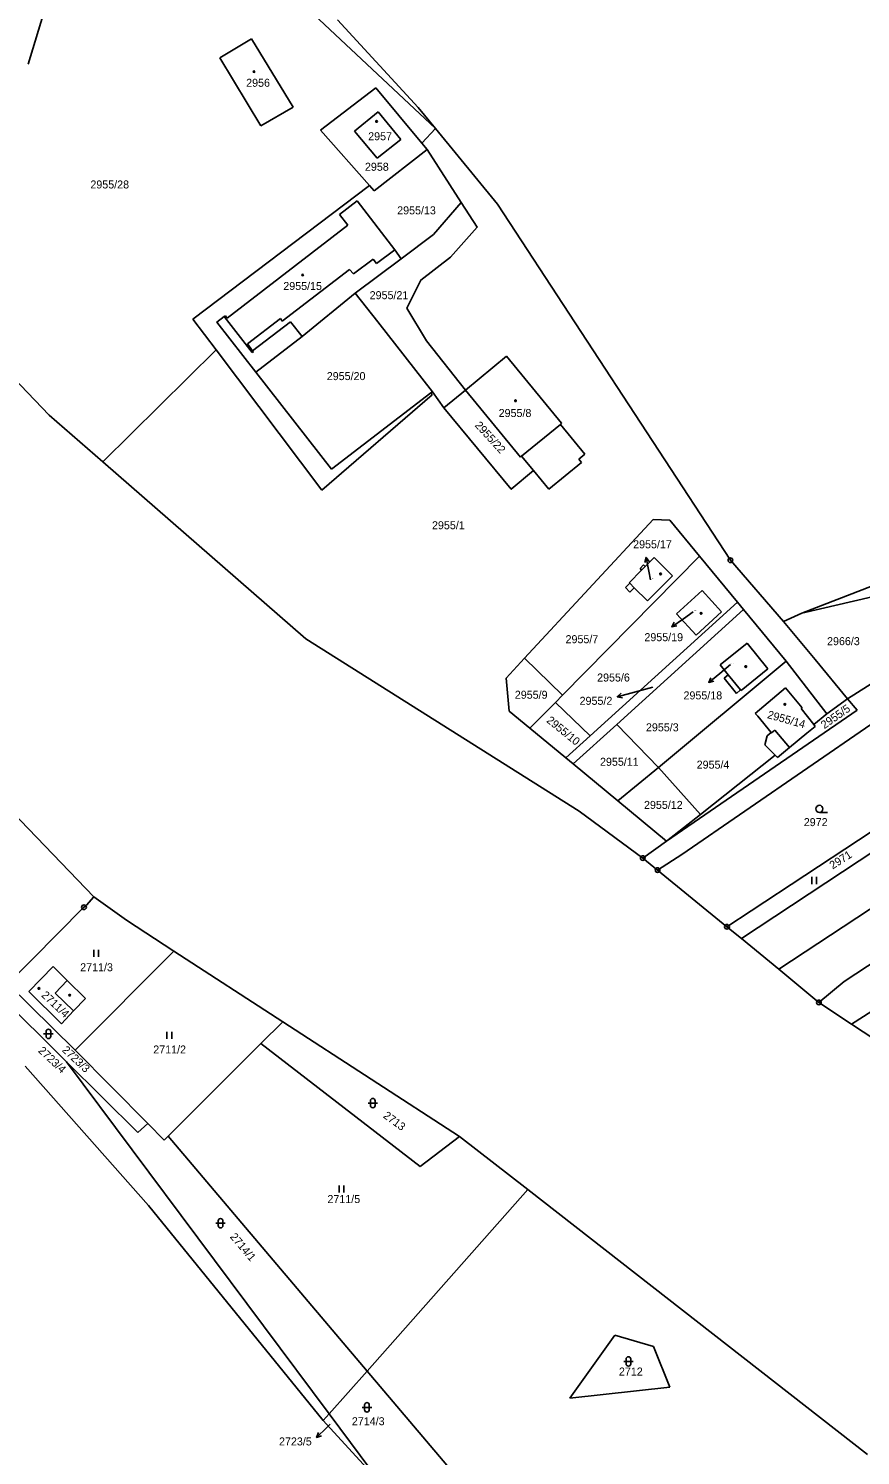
# Model space of a CAD drawing. Extents: x -736345 to -729997, y -1130177 to -1122501.
# Drawn here: x -734414.3 to -734237.6, y -1124788.5 to -1124485.4 of the extents above; entities that cross this region are included whole.
import ezdxf

# ---------------------------------------------------------------- set-up
doc = ezdxf.new("R2010")
doc.units = 0
for name, color, linetype in [('Vrstva 1', 7, 'Continuous'), ('Vrstva 16', 7, 'Continuous'), ('Vrstva 18', 7, 'Continuous'), ('Vrstva 19', 7, 'Continuous'), ('Vrstva 25', 7, 'Continuous'), ('Vrstva 4', 7, 'Continuous')]:
    doc.layers.add(name, color=color, linetype=linetype)

msp = doc.modelspace()

# ---------------------------------------------------------------- linework, layer by layer
at = {"layer": 'Vrstva 1'}
for points in [[(-734371.6, -1124465.53), (-734327.88, -1124506.56)], [(-734410.71, -1124480.82), (-734414.4, -1124492.92)], [(-734348.65, -1124483.52), (-734331.53, -1124502.1)], [(-734366.96, -1124487.53), (-734373.7, -1124491.59)], [(-734358.11, -1124502.09), (-734366.96, -1124487.53)], [(-734373.7, -1124491.59), (-734364.99, -1124506.04)], [(-734340.52, -1124497.94), (-734352.28, -1124506.96)], [(-734330.77, -1124509.7), (-734340.52, -1124497.94)], [(-734358.11, -1124502.09), (-734364.99, -1124506.04)], [(-734331.53, -1124502.1), (-734327.88, -1124506.56)], [(-734345.1, -1124507.19), (-734340.05, -1124503.04)], [(-734340.05, -1124503.04), (-734335.23, -1124508.9)], [(-734352.28, -1124506.96), (-734341.9, -1124518.71)], [(-734340.28, -1124512.86), (-734345.1, -1124507.19)], [(-734330.77, -1124509.7), (-734327.88, -1124506.56)], [(-734327.88, -1124506.56), (-734314.66, -1124522.69)], [(-734329.63, -1124511.08), (-734340.88, -1124519.86)], [(-734335.23, -1124508.9), (-734340.28, -1124512.86)], [(-734329.63, -1124511.08), (-734330.77, -1124509.7)], [(-734329.63, -1124511.08), (-734322.38, -1124522.3)], [(-734341.9, -1124518.71), (-734379.41, -1124547.08)], [(-734340.88, -1124519.86), (-734341.9, -1124518.71)], [(-734348.24, -1124524.87), (-734344.49, -1124521.99)], [(-734344.49, -1124521.99), (-734336.52, -1124532.37)], [(-734322.38, -1124522.3), (-734328.26, -1124529.11), (-734335.13, -1124534.26)], [(-734322.38, -1124522.3), (-734319, -1124527.54), (-734324.64, -1124533.95), (-734330.99, -1124538.79), (-734333.97, -1124544.77), (-734329.79, -1124551.72), (-734321.5, -1124562.16)], [(-734265.19, -1124598.32), (-734314.66, -1124522.69)], [(-734346.48, -1124527.16), (-734348.24, -1124524.87)], [(-734372.15, -1124546.86), (-734346.48, -1124527.16)], [(-734336.52, -1124532.37), (-734335.13, -1124534.26)], [(-734335.13, -1124534.26), (-734344.91, -1124541.55)], [(-734344.91, -1124541.55), (-734356.16, -1124550.76)], [(-734340.13, -1124547.66), (-734344.91, -1124541.55)], [(-734379.41, -1124547.08), (-734374.49, -1124553.6)], [(-734366.04, -1124558.32), (-734374.3, -1124547.72), (-734372.78, -1124546.53)], [(-734372.78, -1124546.53), (-734372.51, -1124546.39)], [(-734372.51, -1124546.39), (-734372.15, -1124546.86)], [(-734328.52, -1124562.5), (-734340.13, -1124547.66)], [(-734366.04, -1124558.32), (-734356.16, -1124550.76)], [(-734398.52, -1124577.43), (-734374.49, -1124553.6)], [(-734374.49, -1124553.6), (-734351.99, -1124583.41)], [(-734312.74, -1124554.97), (-734321.5, -1124562.16)], [(-734301.06, -1124569.21), (-734312.74, -1124554.97)], [(-734409.96, -1124567.46), (-734419.08, -1124557.96)], [(-734349.96, -1124578.95), (-734366.04, -1124558.32)], [(-734351.99, -1124583.41), (-734328.55, -1124563.18)], [(-734328.87, -1124562.77), (-734349.96, -1124578.95)], [(-734328.87, -1124562.77), (-734328.52, -1124562.5)], [(-734328.55, -1124563.18), (-734328.87, -1124562.77)], [(-734328.52, -1124562.5), (-734326.1, -1124565.94)], [(-734321.5, -1124562.16), (-734326.1, -1124565.94)], [(-734321.5, -1124562.16), (-734309.82, -1124576.4)], [(-734326.1, -1124565.94), (-734311.76, -1124583.22), (-734307.05, -1124579.22)], [(-734398.52, -1124577.43), (-734409.96, -1124567.46)], [(-734301.06, -1124569.21), (-734301.32, -1124569.44)], [(-734301.32, -1124569.44), (-734296.12, -1124575.78)], [(-734355.39, -1124615), (-734398.52, -1124577.43)], [(-734309.82, -1124576.4), (-734309.55, -1124576.18)], [(-734309.55, -1124576.18), (-734307.05, -1124579.22)], [(-734296.82, -1124577.53), (-734303.76, -1124583.23)], [(-734296.12, -1124575.78), (-734297.39, -1124576.83)], [(-734297.39, -1124576.83), (-734296.82, -1124577.53)], [(-734307.05, -1124579.22), (-734303.76, -1124583.23)], [(-734281.63, -1124589.62), (-734308.97, -1124619.14)], [(-734278.05, -1124589.82), (-734281.63, -1124589.62)], [(-734271.77, -1124597.44), (-734278.05, -1124589.82)], [(-734212.48, -1124595), (-734250.03, -1124609.57)], [(-734300.84, -1124626.95), (-734271.77, -1124597.44)], [(-734284.4, -1124600.06), (-734283.67, -1124599.29)], [(-734283.67, -1124599.29), (-734283.31, -1124599.64)], [(-734283.31, -1124599.64), (-734281.42, -1124597.71)], [(-734281.42, -1124597.71), (-734277.51, -1124601.59)], [(-734263.68, -1124607.24), (-734271.77, -1124597.44)], [(-734253.92, -1124611.31), (-734265.19, -1124598.32)], [(-734286.67, -1124603.08), (-734284.05, -1124600.4)], [(-734284.05, -1124600.4), (-734284.4, -1124600.06)], [(-734277.51, -1124601.59), (-734282.82, -1124606.92)], [(-734287.48, -1124604.11), (-734286.57, -1124603.19)], [(-734286.53, -1124605.06), (-734287.48, -1124604.11)], [(-734286.57, -1124603.19), (-734286.67, -1124603.08)], [(-734285.61, -1124604.14), (-734286.53, -1124605.06)], [(-734282.82, -1124606.92), (-734285.61, -1124604.14)], [(-734276.62, -1124609.71), (-734271.19, -1124604.76)], [(-734271.19, -1124604.76), (-734267.07, -1124609.3)], [(-734224.12, -1124603.52), (-734250.03, -1124609.57)], [(-734294.98, -1124635.63), (-734263.68, -1124607.24)], [(-734263.68, -1124607.24), (-734262.41, -1124608.78)], [(-734262.41, -1124608.78), (-734289.33, -1124633.19)], [(-734272.5, -1124614.22), (-734276.62, -1124609.71)], [(-734267.07, -1124609.3), (-734272.5, -1124614.22)], [(-734253.34, -1124619.78), (-734262.41, -1124608.78)], [(-734253.92, -1124611.31), (-734250.03, -1124609.57)], [(-734247.21, -1124619.4), (-734253.92, -1124611.31)], [(-734240.3, -1124627.73), (-734215.36, -1124611.96)], [(-734297.35, -1124651.6), (-734355.39, -1124615)], [(-734267.35, -1124620.52), (-734261.66, -1124615.92)], [(-734261.66, -1124615.92), (-734257.26, -1124621.37)], [(-734312.85, -1124623.34), (-734308.97, -1124619.14)], [(-734308.97, -1124619.14), (-734300.84, -1124626.95)], [(-734280.5, -1124642.31), (-734253.34, -1124619.78)], [(-734265.65, -1124622.62), (-734267.35, -1124620.52)], [(-734244.67, -1124630.96), (-734253.34, -1124619.78)], [(-734240.3, -1124627.73), (-734247.21, -1124619.4)], [(-734312.23, -1124630.34), (-734312.85, -1124623.34)], [(-734266.55, -1124623.35), (-734265.65, -1124622.62)], [(-734263.93, -1124626.59), (-734266.55, -1124623.35)], [(-734257.26, -1124621.37), (-734262.94, -1124625.97)], [(-734241, -1124687.82), (-734140.44, -1124621.75)], [(-734263.03, -1124625.86), (-734263.93, -1124626.59)], [(-734262.94, -1124625.97), (-734263.03, -1124625.86)], [(-734259.91, -1124630.83), (-734253.48, -1124625.44)], [(-734253.48, -1124625.44), (-734249.96, -1124629.63)], [(-734302.36, -1124628.51), (-734307.78, -1124634.01)], [(-734300.84, -1124626.95), (-734302.36, -1124628.51)], [(-734294.98, -1124635.63), (-734302.36, -1124628.51)], [(-734249.96, -1124629.63), (-734250.18, -1124629.81)], [(-734250.18, -1124629.81), (-734247.5, -1124633.2)], [(-734244.67, -1124630.96), (-734240.3, -1124627.73)], [(-734238.23, -1124630.16), (-734240.3, -1124627.73)], [(-734130.08, -1124626.92), (-734239.44, -1124696.86)], [(-734307.78, -1124634.01), (-734312.23, -1124630.34)], [(-734278.74, -1124657.95), (-734238.23, -1124630.16)], [(-734259.39, -1124631.45), (-734259.91, -1124630.83)], [(-734259.39, -1124631.45), (-734256.52, -1124634.87)], [(-734172.47, -1124630.93), (-734254.93, -1124685.2)], [(-734244.67, -1124630.96), (-734247.5, -1124633.2)], [(-734307.78, -1124634.01), (-734300.14, -1124640.31)], [(-734300.14, -1124640.31), (-734294.98, -1124635.63)], [(-734289.33, -1124633.19), (-734298.59, -1124641.59)], [(-734289.33, -1124633.19), (-734280.5, -1124642.31)], [(-734275.52, -1124660.81), (-734235.32, -1124633.17)], [(-734257.41, -1124635.61), (-734257.85, -1124637.52)], [(-734256.52, -1124634.87), (-734257.41, -1124635.61)], [(-734252.66, -1124638.09), (-734248.96, -1124635.05)], [(-734248.96, -1124635.05), (-734247.19, -1124633.6)], [(-734247.5, -1124633.2), (-734247.19, -1124633.6)], [(-734255.71, -1124639.71), (-734257.85, -1124637.52)], [(-734255.2, -1124640.23), (-734252.66, -1124638.09)], [(-734298.59, -1124641.59), (-734300.14, -1124640.31)], [(-734298.59, -1124641.59), (-734289.08, -1124649.43)], [(-734255.71, -1124639.71), (-734271.55, -1124652.3)], [(-734255.2, -1124640.23), (-734255.71, -1124639.71)], [(-734289.08, -1124649.43), (-734280.5, -1124642.31)], [(-734280.5, -1124642.31), (-734271.55, -1124652.3)], [(-734215.14, -1124642.77), (-734260.81, -1124672.76)], [(-734262.87, -1124678.67), (-734212.81, -1124645.66)], [(-734278.74, -1124657.95), (-734289.08, -1124649.43)], [(-734400.44, -1124669.79), (-734417.83, -1124651.76)], [(-734283.82, -1124661.59), (-734297.35, -1124651.6)], [(-734271.55, -1124652.3), (-734278.74, -1124657.95)], [(-734283.82, -1124661.59), (-734278.74, -1124657.95)], [(-734280.67, -1124664.12), (-734283.82, -1124661.59)], [(-734280.67, -1124664.12), (-734275.52, -1124660.81)], [(-734265.92, -1124676.18), (-734280.67, -1124664.12)], [(-734402.55, -1124672.03), (-734413.59, -1124683.09)], [(-734401.99, -1124671.57), (-734402.55, -1124672.03)], [(-734401.99, -1124671.57), (-734400.44, -1124669.79)], [(-734400.44, -1124669.79), (-734393.53, -1124674.8)], [(-734393.53, -1124674.8), (-734383.43, -1124681.36)], [(-734260.81, -1124672.76), (-734265.92, -1124676.18)], [(-734265.92, -1124676.18), (-734262.87, -1124678.67)], [(-734404.46, -1124702.4), (-734383.43, -1124681.36)], [(-734383.43, -1124681.36), (-734360.31, -1124696.36)], [(-734262.87, -1124678.67), (-734254.93, -1124685.2)], [(-734413.59, -1124683.09), (-734418.7, -1124688.29)], [(-734414.27, -1124689.94), (-734409.09, -1124684.63)], [(-734409.09, -1124684.63), (-734406.11, -1124687.56)], [(-734254.93, -1124685.2), (-734246.39, -1124692.24)], [(-734420.82, -1124690.51), (-734406.3, -1124704.88)], [(-734404.46, -1124702.4), (-734418.7, -1124688.29)], [(-734407.36, -1124696.77), (-734414.27, -1124689.94)], [(-734406.11, -1124687.56), (-734402.2, -1124691.39)], [(-734246.39, -1124692.24), (-734241, -1124687.82)], [(-734402.2, -1124691.39), (-734404.76, -1124694.06)], [(-734239.44, -1124696.86), (-734246.39, -1124692.24)], [(-734404.76, -1124694.06), (-734407.36, -1124696.77)], [(-734364.96, -1124701), (-734360.31, -1124696.36)], [(-734360.31, -1124696.36), (-734322.76, -1124720.7)], [(-734239.44, -1124696.86), (-734231.79, -1124701.9)], [(-734388.99, -1124717.95), (-734404.46, -1124702.4)], [(-734384.64, -1124720.65), (-734364.96, -1124701)], [(-734331.09, -1124727.11), (-734364.96, -1124701)], [(-734406.3, -1124704.88), (-734391.14, -1124719.89)], [(-734350.44, -1124779.64), (-734406.3, -1124704.88)], [(-734388.81, -1124735.36), (-734415.06, -1124705.8)], [(-734391.14, -1124719.89), (-734388.99, -1124717.95)], [(-734385.48, -1124721.48), (-734388.99, -1124717.95)], [(-734384.64, -1124720.65), (-734385.48, -1124721.48)], [(-734342.38, -1124770.54), (-734384.64, -1124720.65)], [(-734322.76, -1124720.7), (-734331.09, -1124727.11)], [(-734322.76, -1124720.7), (-734308.26, -1124732.01)], [(-734342.38, -1124770.54), (-734308.26, -1124732.01)], [(-734308.26, -1124732.01), (-734236.06, -1124788.31)], [(-734351.7, -1124781.07), (-734388.81, -1124735.36)], [(-734289.74, -1124762.94), (-734299.28, -1124776.31)], [(-734281.51, -1124765.36), (-734289.74, -1124762.94)], [(-734278.03, -1124773.96), (-734281.51, -1124765.36)], [(-734350.44, -1124779.64), (-734342.38, -1124770.54)], [(-734298.26, -1124822.62), (-734342.38, -1124770.54)], [(-734299.28, -1124776.31), (-734278.03, -1124773.96)], [(-734351.7, -1124781.07), (-734350.44, -1124779.64)], [(-734339.3, -1124794.55), (-734351.7, -1124781.07)], [(-734339.3, -1124794.55), (-734350.44, -1124779.64)]]:
    msp.add_lwpolyline(points, dxfattribs=at)
at = {"layer": 'Vrstva 16'}
for points in [[(-734282.15, -1124602.48), (-734282.52, -1124600.66)], [(-734273.13, -1124609.28), (-734275.19, -1124610.72)], [(-734265.18, -1124620.49), (-734267.47, -1124622.37)], [(-734281.71, -1124625.29), (-734286.34, -1124626.54)], [(-734350.25, -1124781.85), (-734350.97, -1124782.55)]]:
    msp.add_lwpolyline(points, dxfattribs=at)
at = {"layer": 'Vrstva 25'}
for points in [[(-734283.405, -1124598.799), (-734283.112, -1124597.72), (-734282.426, -1124598.601)], [(-734282.52, -1124600.66), (-734283.112, -1124597.72)], [(-734275.19, -1124610.72), (-734277.65, -1124612.436)], [(-734276.544, -1124612.274), (-734277.65, -1124612.436), (-734277.116, -1124611.454)], [(-734267.47, -1124622.37), (-734269.788, -1124624.274)], [(-734268.698, -1124624.025), (-734269.788, -1124624.274), (-734269.332, -1124623.253)], [(-734286.34, -1124626.54), (-734289.237, -1124627.316)], [(-734288.142, -1124627.54), (-734289.237, -1124627.316), (-734288.401, -1124626.574)], [(-734246.28, -1124651.87), (-734244.53, -1124651.87)], [(-734247.907, -1124667.085), (-734247.907, -1124665.585)], [(-734246.873, -1124667.085), (-734246.873, -1124665.585)], [(-734400.467, -1124682.535), (-734400.467, -1124681.035)], [(-734399.433, -1124682.535), (-734399.433, -1124681.035)], [(-734411.12, -1124698.92), (-734409.12, -1124698.92)], [(-734410.62, -1124699.42), (-734410.62, -1124698.42)], [(-734409.62, -1124698.42), (-734409.62, -1124699.42)], [(-734384.947, -1124700.005), (-734384.947, -1124698.505)], [(-734383.913, -1124700.005), (-734383.913, -1124698.505)], [(-734342.18, -1124713.63), (-734340.18, -1124713.63)], [(-734341.68, -1124714.13), (-734341.68, -1124713.13)], [(-734340.68, -1124713.13), (-734340.68, -1124714.13)], [(-734348.347, -1124732.625), (-734348.347, -1124731.125)], [(-734347.313, -1124732.625), (-734347.313, -1124731.125)], [(-734374.04, -1124739.65), (-734374.04, -1124738.65)], [(-734373.04, -1124738.65), (-734373.04, -1124739.65)], [(-734374.54, -1124739.15), (-734372.54, -1124739.15)], [(-734287.86, -1124768.5), (-734285.86, -1124768.5)], [(-734287.36, -1124769), (-734287.36, -1124768)], [(-734286.36, -1124768), (-734286.36, -1124769)], [(-734343.42, -1124778.26), (-734341.42, -1124778.26)], [(-734342.92, -1124778.76), (-734342.92, -1124777.76)], [(-734341.92, -1124777.76), (-734341.92, -1124778.76)], [(-734350.97, -1124782.55), (-734353.117, -1124784.645)], [(-734352.052, -1124784.304), (-734353.117, -1124784.645), (-734352.75, -1124783.588)]]:
    msp.add_lwpolyline(points, dxfattribs=at)
for centre, radius in [((-734366.44, -1124494.51), 0.175), ((-734340.39, -1124505.1), 0.175), ((-734356.09, -1124537.7), 0.175), ((-734310.86, -1124564.44), 0.175), ((-734265.19, -1124598.32), 0.5), ((-734265.19, -1124598.32), 0.032), ((-734280.04, -1124601.21), 0.175), ((-734271.42, -1124609.59), 0.175), ((-734261.93, -1124620.89), 0.175), ((-734253.61, -1124628.92), 0.175), ((-734246.28, -1124651.12), 0.75), ((-734283.82, -1124661.59), 0.5), ((-734283.82, -1124661.59), 0.032), ((-734280.67, -1124664.12), 0.5), ((-734280.67, -1124664.12), 0.032), ((-734402.55, -1124672.03), 0.5), ((-734402.55, -1124672.03), 0.032), ((-734265.92, -1124676.18), 0.5), ((-734265.92, -1124676.18), 0.032), ((-734412.14, -1124689.27), 0.175), ((-734405.59, -1124690.7), 0.175), ((-734246.39, -1124692.24), 0.5), ((-734246.39, -1124692.24), 0.032)]:
    msp.add_circle(centre, radius, dxfattribs=at)
for centre, start, end in [((-734410.12, -1124698.42), 0.10099, 180.00143), ((-734410.12, -1124699.42), 180.10243, 0.00286), ((-734341.18, -1124713.13), 0.10099, 180.00143), ((-734341.18, -1124714.13), 180.10243, 0.00286), ((-734373.54, -1124738.65), 0.10099, 180.00143), ((-734373.54, -1124739.65), 180.10243, 0.00286), ((-734286.86, -1124768), 0.10099, 180.00143), ((-734286.86, -1124769), 180.10243, 0.00286), ((-734342.42, -1124777.76), 0.10099, 180.00143), ((-734342.42, -1124778.76), 180.10243, 0.00286)]:
    msp.add_arc(centre, 0.5, start, end, dxfattribs=at)
at = {"layer": 'Vrstva 4'}
for points in [[(-734340.39, -1124535.26), (-734336.52, -1124532.37)], [(-734345.31, -1124537.47), (-734341.12, -1124534.32)], [(-734341.12, -1124534.32), (-734340.39, -1124535.26)], [(-734360.41, -1124547.52), (-734346.12, -1124536.54)], [(-734346.12, -1124536.54), (-734345.31, -1124537.47)], [(-734366.82, -1124554.21), (-734372.78, -1124546.53)], [(-734367.84, -1124552.34), (-734360.79, -1124546.93)], [(-734366.71, -1124553.82), (-734358.69, -1124547.67)], [(-734360.79, -1124546.93), (-734360.41, -1124547.52)], [(-734356.16, -1124550.76), (-734358.69, -1124547.67)], [(-734366.71, -1124553.82), (-734367.84, -1124552.34)], [(-734366.82, -1124554.21), (-734366.56, -1124554.01)], [(-734366.56, -1124554.01), (-734366.71, -1124553.82)], [(-734309.55, -1124576.18), (-734301.32, -1124569.44)], [(-734283.31, -1124599.64), (-734284.05, -1124600.4)], [(-734286.57, -1124603.19), (-734285.61, -1124604.14)], [(-734263.03, -1124625.86), (-734265.65, -1124622.62)], [(-734256.46, -1124634.94), (-734256.52, -1124634.87)], [(-734255.78, -1124634.37), (-734256.46, -1124634.94)], [(-734252.66, -1124638.09), (-734255.78, -1124634.37)], [(-734408.71, -1124690.24), (-734406.11, -1124687.56)], [(-734404.76, -1124694.06), (-734408.71, -1124690.24)]]:
    msp.add_lwpolyline(points, dxfattribs=at)

# ---------------------------------------------------------------- texts
at = {"layer": 'Vrstva 16'}
for s, p in [('2955/17', (-734285.857, -1124595.77)), ('2955/19', (-734283.467, -1124615.5)), ('2966/3', (-734244.657, -1124616.35)), ('2955/18', (-734275.157, -1124627.87)), ('2955/2', (-734297.237, -1124629.02)), ('2723/5', (-734361.107, -1124786.35))]:
    msp.add_text(s, height=1.7, dxfattribs=at).set_placement(p)
at = {"layer": 'Vrstva 18'}
for s, height, p in [('2958', 1.7, (-734342.85, -1124515.57)), ('2955/28', 1.7, (-734401.19, -1124519.33)), ('2955/13', 1.7, (-734336, -1124524.83)), ('2955/21', 1.7, (-734341.848, -1124542.85)), ('2955/20', 1.7, (-734350.958, -1124560.04)), ('2955/1', 1.7, (-734328.6, -1124591.72)), ('2955/7', 1.7, (-734300.22, -1124615.93)), ('2955/6', 1.7, (-734293.51, -1124624.07)), ('2955/9', 1.7, (-734311, -1124627.73)), ('2955/2', 0.1, (-734281.51, -1124625.09)), ('2955/3', 1.7, (-734283.14, -1124634.65)), ('2955/11', 1.7, (-734292.9, -1124641.97)), ('2955/4', 1.7, (-734272.36, -1124642.58)), ('2955/12', 1.7, (-734283.55, -1124651.13)), ('2972', 1.7, (-734249.6, -1124654.79)), ('2711/3', 1.7, (-734403.36, -1124685.62)), ('2711/2', 1.7, (-734387.83, -1124703.09)), ('2711/5', 1.7, (-734350.82, -1124734.86)), ('2712', 1.7, (-734288.88, -1124771.5)), ('2714/3', 1.7, (-734345.63, -1124782.06)), ('2723/5', 0.1, (-734350.05, -1124781.65))]:
    msp.add_text(s, height=height, dxfattribs=at).set_placement(p)
for s, rotation, p in [('2955/22', 312.50249, (-734319.613, -1124569.736)), ('2955/5', 35.10028, (-734245.222, -1124634.202)), ('2955/10', 320.90255, (-734304.409, -1124632.581)), ('2971', 32.30026, (-734243.468, -1124664.005)), ('2723/4', 316.60252, (-734412.408, -1124702.653)), ('2723/3', 316.70252, (-734407.338, -1124702.522)), ('2713', 323.60258, (-734339.111, -1124716.598)), ('2714/1', 310.20247, (-734371.639, -1124742.083))]:
    msp.add_text(s, height=1.7, rotation=rotation, dxfattribs=at).set_placement(p)
at = {"layer": 'Vrstva 19'}
for s, height, p in [('2956', 1.7, (-734368.09, -1124497.73)), ('2957', 1.7, (-734342.16, -1124509.09)), ('2955/15', 1.7, (-734360.2, -1124540.9)), ('2955/8', 1.7, (-734314.44, -1124567.88)), ('2955/17', 0.1, (-734281.95, -1124602.28)), ('2955/19', 0.1, (-734272.93, -1124609.08)), ('2955/18', 0.1, (-734264.98, -1124620.29))]:
    msp.add_text(s, height=height, dxfattribs=at).set_placement(p)
for s, rotation, p in [('2955/14', 344.40274, (-734257.464, -1124631.822)), ('2711/4', 316.80252, (-734411.728, -1124690.872))]:
    msp.add_text(s, height=1.7, rotation=rotation, dxfattribs=at).set_placement(p)

doc.saveas('drawing.dxf')
